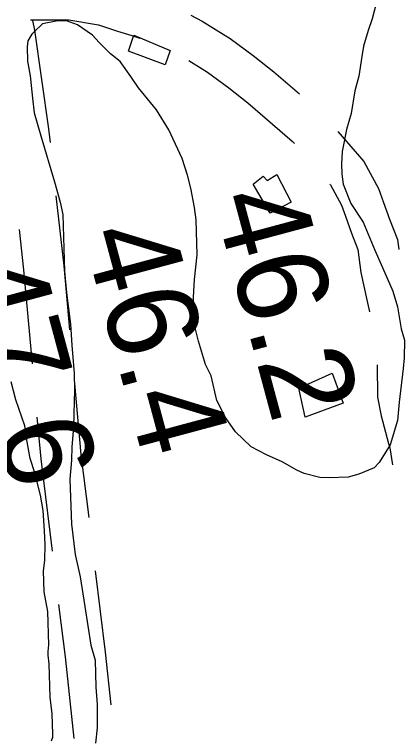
# Model space of a CAD drawing. Extents: x 3250478 to 3288318, y 788638 to 816472.
# Drawn here: x 3278906 to 3279195, y 796276 to 796815 of the extents above; entities that cross this region are included whole.
import ezdxf

# ---------------------------------------------------------------- set-up
doc = ezdxf.new("R2010")
doc.units = 0
for name, color, linetype in [('V-BLDG-OTLN', 7, 'Continuous'), ('V-RIVR-RANG', 7, 'Continuous'), ('V-ROAD-CNTR', 7, 'Continuous'), ('V-SITE-VEGE', 7, 'Continuous')]:
    doc.layers.add(name, color=color, linetype=linetype)

msp = doc.modelspace()

# ---------------------------------------------------------------- linework, layer by layer
at = {"layer": 'V-BLDG-OTLN'}
for points in [[(3278990.51, 796787.3), (3278994.35, 796799.2), (3279021.45, 796787.83), (3279017.58, 796777.13)], [(3279095.58, 796667.01), (3279082.95, 796688.6), (3279090.36, 796694.62), (3279093.25, 796691.31), (3279100.51, 796695.72), (3279111.11, 796675.27)], [(3279121.49, 796515.59), (3279116.84, 796537.22), (3279141.48, 796548.34), (3279149.74, 796526.02)]]:
    msp.add_lwpolyline(points, close=True, dxfattribs=at)
at = {"layer": 'V-ROAD-CNTR'}
for points in [[(3279036.6, 796814.18), (3279045.03, 796809.53), (3279065.89, 796796.66), (3279083.06, 796784.11), (3279098.2, 796772.1), (3279117.24, 796755.63)], [(3278917.79, 796810.74), (3278946.31, 796810.63), (3278968.24, 796806.85), (3278982.28, 796802.21), (3278993.04, 796798.98), (3278996.65, 796797.75), (3278998.94, 796797.06)], [(3278919.24, 796810.18), (3278920.67, 796802.89), (3278931.2, 796729.64), (3278932.31, 796719.62)], [(3279035.13, 796780.39), (3279049.13, 796771.75), (3279064.88, 796760.24), (3279079.05, 796749), (3279111.99, 796720.5), (3279113.5, 796718.78)], [(3279145.63, 796727.6), (3279165.1, 796705.33), (3279175.87, 796685.3), (3279179.68, 796674.94), (3279184.02, 796662.69), (3279189.94, 796647.48), (3279190.87, 796640.21)], [(3279139.82, 796688.66), (3279140.28, 796688.14), (3279148.44, 796672.97), (3279151.46, 796664.75), (3279155.9, 796652.23), (3279160.64, 796640.03), (3279162.82, 796622.98), (3279167.14, 796602.73), (3279169.14, 796593.9)], [(3278936.68, 796679.86), (3278942.4, 796627.91), (3278946.73, 796580.37)], [(3278909.25, 796654.86), (3278912.55, 796624.91), (3278918.89, 796555.33)], [(3279174.9, 796554.43), (3279175.28, 796530.52), (3279177.77, 796516.64), (3279183.43, 796496.17), (3279184.24, 796492.95), (3279186.32, 796480.24)], [(3278950.36, 796540.54), (3278955.17, 796487.77), (3278960.92, 796441.11)], [(3278922.52, 796515.5), (3278925.33, 796484.57), (3278933.77, 796416.14)], [(3278965.81, 796401.41), (3278973.23, 796341.2), (3278977.45, 796302.1)], [(3278938.66, 796376.45), (3278943.43, 796337.75), (3278949.98, 796277.09)]]:
    msp.add_lwpolyline(points, dxfattribs=at)
at = {"layer": 'V-SITE-VEGE'}
for p, q in [((3279174.19, 796822.75), (3279171.29, 796811.32)), ((3278936.88, 796809.7), (3278926.68, 796807.78)), ((3278944.44, 796809.93), (3278936.88, 796809.7)), ((3278952.63, 796806.93), (3278944.44, 796809.93)), ((3279171.29, 796811.32), (3279168.31, 796802.59)), ((3278926.68, 796807.78), (3278920.37, 796801.64)), ((3278963.67, 796799.16), (3278952.63, 796806.93)), ((3278918.81, 796799.98), (3278915.71, 796795.02)), ((3278920.37, 796801.64), (3278918.81, 796799.98)), ((3278968.69, 796793.91), (3278963.67, 796799.16)), ((3279168.31, 796802.59), (3279164.87, 796791.14)), ((3278915.71, 796795.02), (3278915.3, 796790.69)), ((3278977.04, 796785.51), (3278968.69, 796793.91)), ((3278915.3, 796790.69), (3278915.62, 796779.89)), ((3279164.87, 796791.14), (3279163.48, 796783.53)), ((3278984.24, 796779.79), (3278977.04, 796785.51)), ((3279163.48, 796783.53), (3279161.22, 796768.88)), ((3278915.62, 796779.89), (3278917.56, 796769.15)), ((3278992.13, 796768.68), (3278984.24, 796779.79)), ((3278917.56, 796769.15), (3278919.15, 796752.45)), ((3278997.79, 796760.21), (3278992.13, 796768.68)), ((3279161.22, 796768.88), (3279158.3, 796757.99)), ((3279011.24, 796743.86), (3278997.79, 796760.21)), ((3279158.3, 796757.99), (3279155.56, 796741.16)), ((3278919.15, 796752.45), (3278920.55, 796741.69)), ((3279020.33, 796729.01), (3279011.24, 796743.86)), ((3278920.55, 796741.69), (3278925.39, 796724.54)), ((3279155.56, 796741.16), (3279152.14, 796729.17)), ((3279030.15, 796707.69), (3279020.33, 796729.01)), ((3279152.14, 796729.17), (3279148.85, 796712.86)), ((3278925.39, 796724.54), (3278935.59, 796690.28)), ((3279148.85, 796712.86), (3279148.58, 796703.67)), ((3279034.3, 796695.39), (3279030.15, 796707.69)), ((3279148.58, 796703.67), (3279148.81, 796696.12)), ((3279036.75, 796685.74), (3279034.3, 796695.39)), ((3279148.81, 796696.12), (3279149.58, 796688.58)), ((3278935.59, 796690.28), (3278939.83, 796675.28)), ((3279039.35, 796671.23), (3279036.75, 796685.74)), ((3279149.58, 796688.58), (3279155.41, 796674.17)), ((3278939.83, 796675.28), (3278941.72, 796666.15)), ((3279155.41, 796674.17), (3279164.46, 796660.39)), ((3279040.7, 796662.09), (3279039.35, 796671.23)), ((3278941.72, 796666.15), (3278942.98, 796624.05)), ((3279041.48, 796636.18), (3279040.7, 796662.09)), ((3279164.46, 796660.39), (3279173.19, 796639.58)), ((3279039.33, 796617.75), (3279041.48, 796636.18)), ((3279173.19, 796639.58), (3279178.98, 796626.79)), ((3279178.98, 796626.79), (3279186.53, 796609.19)), ((3278942.98, 796624.05), (3278944.54, 796607.89)), ((3279038.64, 796604.76), (3279039.33, 796617.75)), ((3279186.53, 796609.19), (3279190.12, 796597.41)), ((3278944.54, 796607.89), (3278947.4, 796584.74)), ((3279039.23, 796584.79), (3279038.64, 796604.76)), ((3279190.12, 796597.41), (3279192.77, 796581.29)), ((3278947.4, 796584.74), (3278948.41, 796569.11)), ((3279042.32, 796571.92), (3279039.23, 796584.79)), ((3279192.77, 796581.29), (3279195.18, 796572.71)), ((3279047.7, 796554.79), (3279042.32, 796571.92)), ((3279195.18, 796572.71), (3279195.03, 796559.74)), ((3278948.41, 796569.11), (3278950.12, 796548.09)), ((3279195.03, 796559.74), (3279194.2, 796551.62)), ((3279051.74, 796546.27), (3279047.7, 796554.79)), ((3279194.2, 796551.62), (3279191.16, 796526.67)), ((3278950.12, 796548.09), (3278950.49, 796535.67)), ((3279056.06, 796528.03), (3279051.74, 796546.27)), ((3278906.95, 796528.43), (3278903.31, 796541.82)), ((3278950.49, 796535.67), (3278949.93, 796518.37)), ((3278913.46, 796509.18), (3278906.95, 796528.43)), ((3279062.39, 796515.25), (3279056.06, 796528.03)), ((3279191.16, 796526.67), (3279189.94, 796513.13)), ((3278949.93, 796518.37), (3278949.69, 796508.1)), ((3279069.73, 796504.67), (3279062.39, 796515.25)), ((3279189.94, 796513.13), (3279184.54, 796495.14)), ((3278914.82, 796500.03), (3278913.46, 796509.18)), ((3278949.69, 796508.1), (3278948.51, 796493.47)), ((3279081.4, 796493.67), (3279069.73, 796504.67)), ((3278917.43, 796484.98), (3278914.82, 796500.03)), ((3278948.51, 796493.47), (3278948.26, 796483.74)), ((3279092.93, 796487.54), (3279081.4, 796493.67)), ((3279184.54, 796495.14), (3279176.29, 796481.93)), ((3279104.43, 796482.48), (3279092.93, 796487.54)), ((3278920.99, 796474.29), (3278917.43, 796484.98)), ((3278948.26, 796483.74), (3278947.06, 796469.66)), ((3279115.42, 796476.32), (3279104.43, 796482.48)), ((3279176.29, 796481.93), (3279172.62, 796478.04)), ((3279120.89, 796473.79), (3279115.42, 796476.32)), ((3279172.62, 796478.04), (3279161.42, 796473.38)), ((3278925.27, 796457.67), (3278920.99, 796474.29)), ((3278947.06, 796469.66), (3278948.06, 796436.2)), ((3279132.33, 796470.89), (3279120.89, 796473.79)), ((3279139.36, 796470.56), (3279132.33, 796470.89)), ((3279153.39, 796470.98), (3279139.36, 796470.56)), ((3279161.42, 796473.38), (3279153.39, 796470.98)), ((3278927.23, 796446.38), (3278925.27, 796457.67)), ((3278928.22, 796431.28), (3278927.23, 796446.38)), ((3278948.06, 796436.2), (3278950.9, 796413.59)), ((3278928.53, 796421.03), (3278928.22, 796431.28)), ((3278928.35, 796409.14), (3278928.53, 796421.03)), ((3278950.9, 796413.59), (3278954.64, 796396.96)), ((3278927.49, 796401.55), (3278928.35, 796409.14)), ((3278927.96, 796385.89), (3278927.49, 796401.55)), ((3278954.64, 796396.96), (3278958, 796374.91)), ((3278930.56, 796371.39), (3278927.96, 796385.89)), ((3278958, 796374.91), (3278962.64, 796346.42)), ((3278931.3, 796346.56), (3278930.56, 796371.39)), ((3278930.91, 796341.68), (3278931.3, 796346.56)), ((3278962.64, 796346.42), (3278965.68, 796335.17)), ((3278930.99, 796338.99), (3278930.91, 796341.68)), ((3278931.72, 796332.53), (3278930.99, 796338.99)), ((3278965.68, 796335.17), (3278966.27, 796315.19)), ((3278932.46, 796307.7), (3278931.72, 796332.53)), ((3278966.27, 796315.19), (3278967.2, 796302.26)), ((3278933.92, 796295.32), (3278932.46, 796307.7)), ((3278967.2, 796302.26), (3278967.18, 796284.97)), ((3278934.37, 796280.2), (3278933.92, 796295.32)), ((3278967.18, 796284.97), (3278965.9, 796273.58)), ((3278933.44, 796275.31), (3278934.43, 796278.04)), ((3278934.43, 796278.04), (3278934.37, 796280.2))]:
    msp.add_line(p, q, dxfattribs=at)

# ---------------------------------------------------------------- texts
at = {"layer": 'V-RIVR-RANG'}
for s, p in [('46.2', (3279052.9, 796677.67)), ('46.4', (3278956.39, 796651.48)), ('47.6', (3278859.4, 796627.06))]:
    msp.add_text(s, height=67, rotation=285.0483, dxfattribs=at).set_placement(p)

doc.saveas('drawing.dxf')
